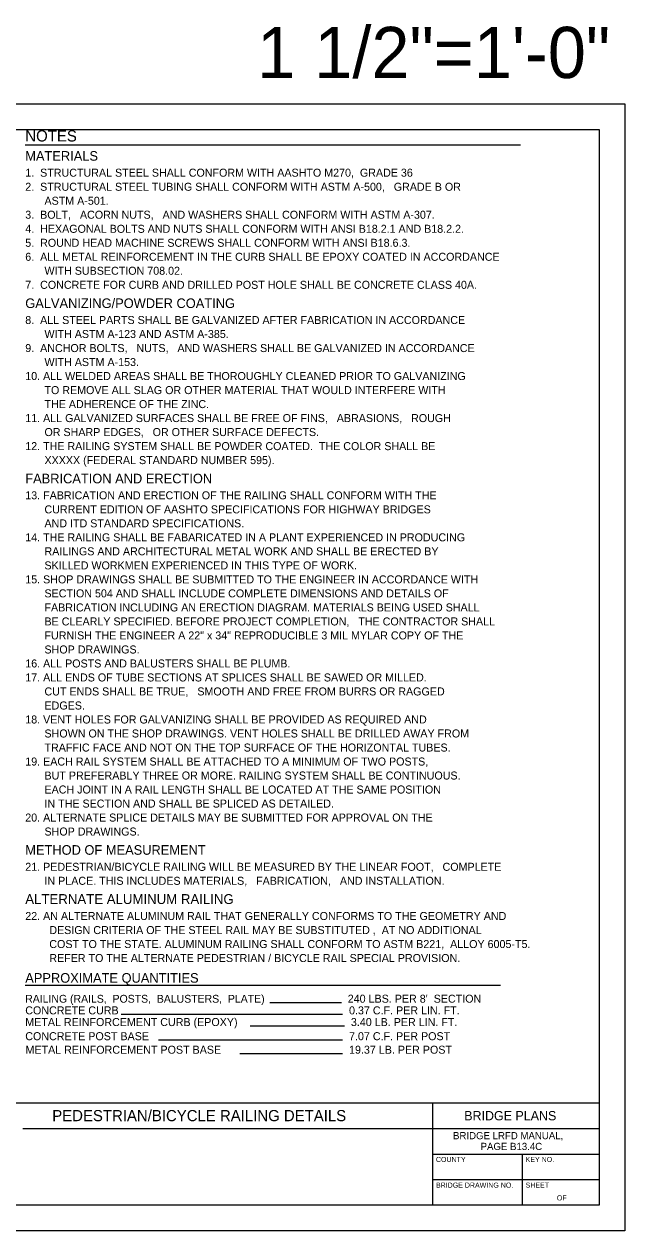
# Model space of a CAD drawing. Extents: x 0 to 22.7, y 0 to 15.7.
# Drawn here: x 14.85 to 22.67, y 0 to 15.7 of the extents above; entities that cross this region are included whole.
import ezdxf

# ---------------------------------------------------------------- set-up
doc = ezdxf.new("R2010")
doc.units = 0
for name, color, linetype in [('BORDER_ANNO_Cutsheet', 7, 'Continuous'), ('BRDG_ANNO_Anno-Sheet', 7, 'Continuous'), ('BRDG_ANNO_General-Notes', 7, 'Continuous')]:
    doc.layers.add(name, color=color, linetype=linetype)

msp = doc.modelspace()

# ---------------------------------------------------------------- linework, layer by layer
at = {"layer": 'BORDER_ANNO_Cutsheet'}
msp.add_lwpolyline([(0, 14.667), (22.667, 14.667), (22.667, 0), (0, 0)], close=True, dxfattribs=at)
at = {"layer": 'BRDG_ANNO_Anno-Sheet'}
for p, q in [((12.833, 1.667), (22.333, 1.667)), ((20.167, 0.333), (20.167, 1.667)), ((14.833, 1.333), (20.167, 1.333)), ((20.167, 1.333), (22.333, 1.333)), ((20.167, 1), (22.333, 1)), ((21.333, 0.333), (21.333, 1)), ((20.167, 0.667), (22.333, 0.667))]:
    msp.add_line(p, q, dxfattribs=at)
msp.add_lwpolyline([(1, 14.333), (22.333, 14.333), (22.333, 0.333), (1, 0.333)], close=True, dxfattribs=at)
at = {"layer": 'BRDG_ANNO_General-Notes'}
for p, q in [((14.863, 14.133), (21.31, 14.133)), ((14.863, 3.198), (21.046, 3.198)), ((18.977, 2.969), (18.044, 2.969)), ((18.993, 2.817), (16.112, 2.817)), ((19.018, 2.665), (17.79, 2.665)), ((18.993, 2.481), (16.596, 2.481)), ((18.993, 2.305), (17.656, 2.305))]:
    msp.add_line(p, q, dxfattribs=at)

# ---------------------------------------------------------------- texts
at = {"layer": 'BRDG_ANNO_Anno-Sheet'}
for s, height, p in [('1 1/2"=1\'-0"', 0.66667, (17.881, 15)), ('PEDESTRIAN/BICYCLE RAILING DETAILS', 0.14542, (15.214, 1.427)), ('BRIDGE PLANS', 0.12125, (20.576, 1.438)), ('BRIDGE LRFD MANUAL,', 0.09375, (20.43, 1.192)), ('PAGE B13.4C', 0.09375, (20.789, 1.052)), ('COUNTY', 0.0663, (20.208, 0.896)), ('KEY NO.', 0.0663, (21.375, 0.896)), ('BRIDGE DRAWING NO.', 0.06625, (20.208, 0.562)), ('SHEET', 0.0663, (21.375, 0.562)), ('OF', 0.0663, (21.781, 0.396))]:
    msp.add_text(s, height=height, dxfattribs=at).set_placement(p)
at = {"layer": 'BRDG_ANNO_General-Notes'}
for s, height, p in [('NOTES', 0.1458, (14.863, 14.175)), ('MATERIALS', 0.1249, (14.863, 13.925)), ('1.  STRUCTURAL STEEL SHALL CONFORM WITH AASHTO M270,  GRADE 36', 0.10411, (14.863, 13.717)), ('2.  STRUCTURAL STEEL TUBING SHALL CONFORM WITH ASTM A-500,   GRADE B OR', 0.10411, (14.863, 13.534)), ('ASTM A-501.', 0.10411, (15.113, 13.352)), ('3.  BOLT,   ACORN NUTS,   AND WASHERS SHALL CONFORM WITH ASTM A-307.', 0.10411, (14.863, 13.17)), ('4.  HEXAGONAL BOLTS AND NUTS SHALL CONFORM WITH ANSI B18.2.1 AND B18.2.2.', 0.10411, (14.863, 12.987)), ('5.  ROUND HEAD MACHINE SCREWS SHALL CONFORM WITH ANSI B18.6.3.', 0.10411, (14.863, 12.805)), ('6.  ALL METAL REINFORCEMENT IN THE CURB SHALL BE EPOXY COATED IN ACCORDANCE', 0.10411, (14.863, 12.623)), ('WITH SUBSECTION 708.02.', 0.10411, (15.113, 12.441)), ('7.  CONCRETE FOR CURB AND DRILLED POST HOLE SHALL BE CONCRETE CLASS 40A.', 0.10411, (14.863, 12.258)), ('GALVANIZING/POWDER COATING', 0.12495, (14.863, 12.008)), ('8.  ALL STEEL PARTS SHALL BE GALVANIZED AFTER FABRICATION IN ACCORDANCE ', 0.10411, (14.863, 11.8)), ('WITH ASTM A-123 AND ASTM A-385.', 0.10411, (15.113, 11.618)), ('9.  ANCHOR BOLTS,   NUTS,   AND WASHERS SHALL BE GALVANIZED IN ACCORDANCE', 0.10411, (14.863, 11.435)), ('WITH ASTM A-153.', 0.10411, (15.113, 11.253)), ('10. ALL WELDED AREAS SHALL BE THOROUGHLY CLEANED PRIOR TO GALVANIZING', 0.10411, (14.863, 11.071)), ('TO REMOVE ALL SLAG OR OTHER MATERIAL THAT WOULD INTERFERE WITH', 0.10411, (15.113, 10.888)), ('THE ADHERENCE OF THE ZINC.', 0.10411, (15.113, 10.706)), ('11. ALL GALVANIZED SURFACES SHALL BE FREE OF FINS,   ABRASIONS,   ROUGH', 0.10411, (14.863, 10.524)), ('OR SHARP EDGES,   OR OTHER SURFACE DEFECTS.', 0.10411, (15.113, 10.342)), ('12. THE RAILING SYSTEM SHALL BE POWDER COATED.  THE COLOR SHALL BE', 0.10411, (14.863, 10.159)), ('XXXXX (FEDERAL STANDARD NUMBER 595).', 0.10411, (15.113, 9.977)), ('FABRICATION AND ERECTION', 0.12495, (14.863, 9.727)), ('13. FABRICATION AND ERECTION OF THE RAILING SHALL CONFORM WITH THE', 0.10411, (14.863, 9.519)), ('CURRENT EDITION OF AASHTO SPECIFICATIONS FOR HIGHWAY BRIDGES  ', 0.10411, (15.113, 9.336)), ('AND ITD STANDARD SPECIFICATIONS.', 0.10411, (15.113, 9.154)), ('14. THE RAILING SHALL BE FABARICATED IN A PLANT EXPERIENCED IN PRODUCING', 0.10411, (14.863, 8.972)), ('RAILINGS AND ARCHITECTURAL METAL WORK AND SHALL BE ERECTED BY ', 0.10411, (15.113, 8.79)), ('SKILLED WORKMEN EXPERIENCED IN THIS TYPE OF WORK. ', 0.10411, (15.113, 8.607)), ('15. SHOP DRAWINGS SHALL BE SUBMITTED TO THE ENGINEER IN ACCORDANCE WITH', 0.10411, (14.863, 8.425)), ('SECTION 504 AND SHALL INCLUDE COMPLETE DIMENSIONS AND DETAILS OF', 0.10411, (15.113, 8.243)), ('FABRICATION INCLUDING AN ERECTION DIAGRAM. MATERIALS BEING USED SHALL', 0.10411, (15.113, 8.06)), ('BE CLEARLY SPECIFIED. BEFORE PROJECT COMPLETION,   THE CONTRACTOR SHALL', 0.10411, (15.113, 7.878)), ('FURNISH THE ENGINEER A 22" x 34" REPRODUCIBLE 3 MIL MYLAR COPY OF THE', 0.10411, (15.113, 7.696)), ('SHOP DRAWINGS.', 0.10411, (15.113, 7.513)), ('16. ALL POSTS AND BALUSTERS SHALL BE PLUMB.', 0.10411, (14.863, 7.331)), ('17. ALL ENDS OF TUBE SECTIONS AT SPLICES SHALL BE SAWED OR MILLED.', 0.10417, (14.863, 7.149)), ('CUT ENDS SHALL BE TRUE,   SMOOTH AND FREE FROM BURRS OR RAGGED', 0.10417, (15.113, 6.967)), ('EDGES.', 0.1042, (15.113, 6.784)), ('18. VENT HOLES FOR GALVANIZING SHALL BE PROVIDED AS REQUIRED AND', 0.10417, (14.863, 6.602)), ('SHOWN ON THE SHOP DRAWINGS. VENT HOLES SHALL BE DRILLED AWAY FROM', 0.10417, (15.113, 6.42)), ('TRAFFIC FACE AND NOT ON THE TOP SURFACE OF THE HORIZONTAL TUBES.', 0.10417, (15.113, 6.237)), ('19. EACH RAIL SYSTEM SHALL BE ATTACHED TO A MINIMUM OF TWO POSTS,', 0.10411, (14.863, 6.055)), ('BUT PREFERABLY THREE OR MORE. RAILING SYSTEM SHALL BE CONTINUOUS.', 0.10411, (15.113, 5.873)), ('EACH JOINT IN A RAIL LENGTH SHALL BE LOCATED AT THE SAME POSITION', 0.10411, (15.113, 5.691)), ('IN THE SECTION AND SHALL BE SPLICED AS DETAILED.', 0.10411, (15.113, 5.508)), ('20. ALTERNATE SPLICE DETAILS MAY BE SUBMITTED FOR APPROVAL ON THE', 0.10417, (14.863, 5.326)), ('SHOP DRAWINGS.', 0.10417, (15.113, 5.144)), ('METHOD OF MEASUREMENT', 0.12495, (14.863, 4.894)), ('21. PEDESTRIAN/BICYCLE RAILING WILL BE MEASURED BY THE LINEAR FOOT,   COMPLETE', 0.10411, (14.863, 4.685)), ('IN PLACE. THIS INCLUDES MATERIALS,   FABRICATION,   AND INSTALLATION.', 0.10411, (15.113, 4.503)), ('ALTERNATE ALUMINUM RAILING', 0.12858, (14.863, 4.253)), ('22. AN ALTERNATE ALUMINUM RAIL THAT GENERALLY CONFORMS TO THE GEOMETRY AND', 0.10416, (14.863, 4.045)), ('DESIGN CRITERIA OF THE STEEL RAIL MAY BE SUBSTITUTED ,  AT NO ADDITIONAL', 0.10416, (15.176, 3.862)), ('COST TO THE STATE. ALUMINUM RAILING SHALL CONFORM TO ASTM B221,  ALLOY 6005-T5.', 0.10416, (15.176, 3.68)), ('REFER TO THE ALTERNATE PEDESTRIAN / BICYCLE RAIL SPECIAL PROVISION.', 0.10416, (15.176, 3.498)), ('APPROXIMATE QUANTITIES', 0.12494, (14.863, 3.229)), ('RAILING (RAILS,  POSTS,  BALUSTERS,  PLATE)', 0.10203, (14.862, 2.969)), ("240 LBS. PER 8'  SECTION", 0.10417, (19.06, 2.969)), ('CONCRETE CURB', 0.10417, (14.863, 2.817)), ('0.37 C.F. PER LIN. FT.', 0.10417, (19.077, 2.817)), ('METAL REINFORCEMENT CURB (EPOXY)', 0.10417, (14.863, 2.665)), ('3.40 LB. PER LIN. FT.', 0.10417, (19.101, 2.665)), ('CONCRETE POST BASE', 0.10417, (14.863, 2.481)), ('7.07 C.F. PER POST', 0.10417, (19.077, 2.481)), ('METAL REINFORCEMENT POST BASE', 0.10417, (14.866, 2.305)), ('19.37 LB. PER POST', 0.10417, (19.077, 2.305))]:
    msp.add_text(s, height=height, dxfattribs=at).set_placement(p)

doc.saveas('drawing.dxf')
